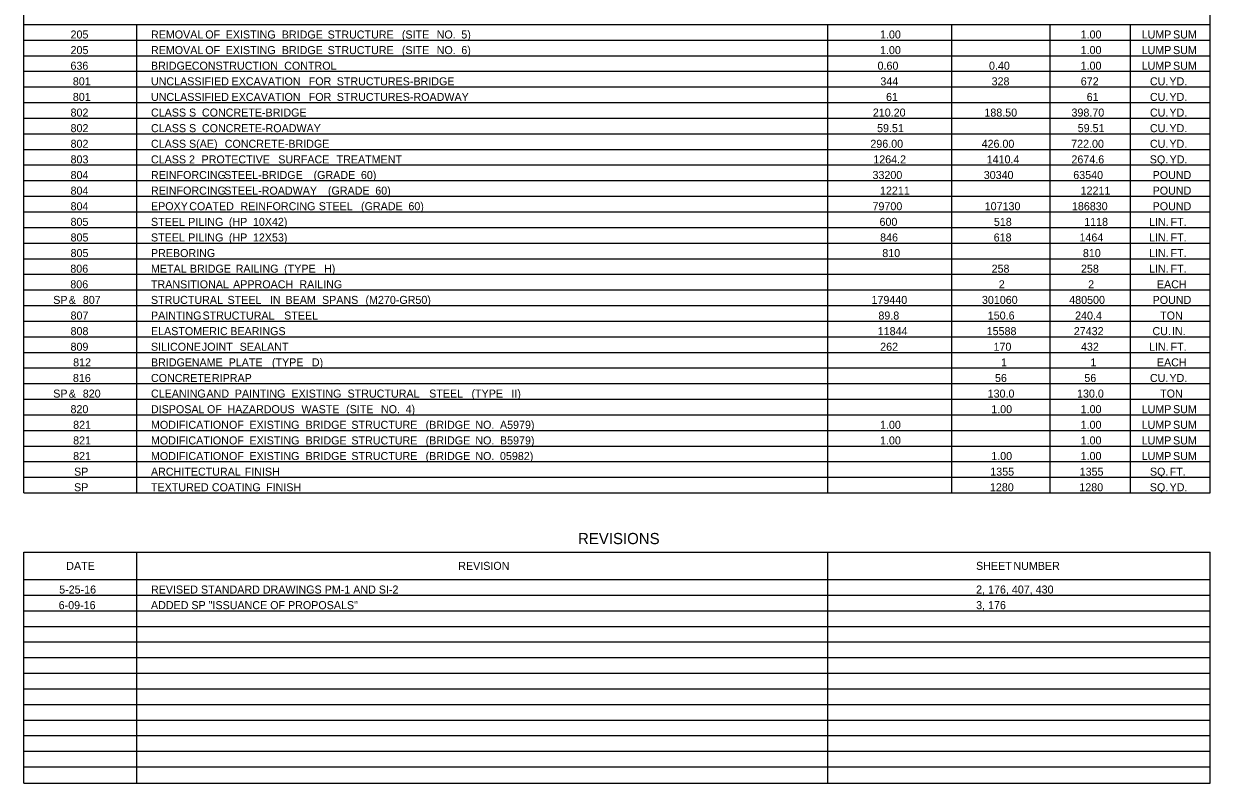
# Model space of a CAD drawing. Extents: x 1226912 to 1228117, y 151309 to 152323.
# Drawn here: x 1226912 to 1227653, y 151388 to 151863 of the extents above; entities that cross this region are included whole.
import ezdxf

# ---------------------------------------------------------------- set-up
doc = ezdxf.new("R2010")
doc.units = 0
doc.layers.add('R_Dimension', color=7, linetype='Continuous')

msp = doc.modelspace()

# ---------------------------------------------------------------- linework, layer by layer
at = {"layer": 'R_Dimension'}
for p, q in [((1226912.03, 151569.59), (1226912.03, 152184.82)), ((1227653.03, 151569.59), (1227653.03, 152184.82)), ((1226912.03, 151862.09), (1227653.03, 151862.09)), ((1226982.72, 151569.59), (1226982.72, 151862.09)), ((1227414.15, 151569.59), (1227414.15, 151862.09)), ((1227491.67, 151569.59), (1227491.67, 151862.09)), ((1227553.09, 151569.59), (1227553.09, 151862.09)), ((1227603.3, 151569.59), (1227603.3, 151862.09)), ((1226912.03, 151852.34), (1227653.03, 151852.34)), ((1226912.03, 151842.59), (1227653.03, 151842.59)), ((1226912.03, 151832.84), (1227653.03, 151832.84)), ((1226912.03, 151823.09), (1227653.03, 151823.09)), ((1226912.03, 151813.34), (1227653.03, 151813.34)), ((1226912.03, 151803.59), (1227653.03, 151803.59)), ((1226912.03, 151793.84), (1227653.03, 151793.84)), ((1226912.03, 151784.09), (1227653.03, 151784.09)), ((1226912.03, 151774.34), (1227653.03, 151774.34)), ((1226912.03, 151764.59), (1227653.03, 151764.59)), ((1226912.03, 151754.84), (1227653.03, 151754.84)), ((1226912.03, 151745.09), (1227653.03, 151745.09)), ((1226912.03, 151735.34), (1227653.03, 151735.34)), ((1226912.03, 151725.59), (1227653.03, 151725.59)), ((1226912.03, 151715.84), (1227653.03, 151715.84)), ((1226912.03, 151706.09), (1227653.03, 151706.09)), ((1226912.03, 151696.34), (1227653.03, 151696.34)), ((1226912.03, 151686.59), (1227653.03, 151686.59)), ((1226912.03, 151676.84), (1227653.03, 151676.84)), ((1226912.03, 151667.09), (1227653.03, 151667.09)), ((1226912.03, 151657.34), (1227653.03, 151657.34)), ((1226912.03, 151647.59), (1227653.03, 151647.59)), ((1226912.03, 151637.84), (1227653.03, 151637.84)), ((1226912.03, 151628.09), (1227653.03, 151628.09)), ((1226912.03, 151618.34), (1227653.03, 151618.34)), ((1226912.03, 151608.59), (1227653.03, 151608.59)), ((1226912.03, 151598.84), (1227653.03, 151598.84)), ((1226912.03, 151589.09), (1227653.03, 151589.09)), ((1226912.03, 151579.34), (1227653.03, 151579.34)), ((1226912.03, 151569.59), (1227653.03, 151569.59)), ((1226912.03, 151532.54), (1227653.03, 151532.54)), ((1226912.03, 151388.24), (1226912.03, 151532.54)), ((1226982.72, 151388.24), (1226982.72, 151532.54)), ((1227414.15, 151388.24), (1227414.15, 151532.54)), ((1227653.03, 151388.24), (1227653.03, 151532.54)), ((1226912.03, 151515.48), (1227653.03, 151515.48)), ((1226912.03, 151505.73), (1227653.03, 151505.73)), ((1226912.03, 151495.98), (1227653.03, 151495.98)), ((1226912.03, 151486.23), (1227653.03, 151486.23)), ((1226912.03, 151476.48), (1227653.03, 151476.48)), ((1226912.03, 151466.73), (1227653.03, 151466.73)), ((1226912.03, 151456.98), (1227653.03, 151456.98)), ((1226912.03, 151447.23), (1227653.03, 151447.23)), ((1226912.03, 151437.48), (1227653.03, 151437.48)), ((1226912.03, 151427.73), (1227653.03, 151427.73)), ((1226912.03, 151417.98), (1227653.03, 151417.98)), ((1226912.03, 151408.23), (1227653.03, 151408.23)), ((1226912.03, 151398.48), (1227653.03, 151398.48)), ((1226912.03, 151388.24), (1227653.03, 151388.24))]:
    msp.add_line(p, q, dxfattribs=at)

# ---------------------------------------------------------------- texts
for s, height, p in [('205', 5, (1226941.27, 151853.34)), ('REMOVAL', 5, (1226991.49, 151853.34)), (' OF', 5, (1227023.54, 151853.34)), (' EXISTING', 5, (1227036.3, 151853.34)), (' BRIDGE', 5, (1227071.33, 151853.34)), (' STRUCTURE', 5, (1227099.96, 151853.34)), (' (SITE', 5, (1227146.3, 151853.34)), (' NO.', 5, (1227168.07, 151853.34)), (' 5)', 5, (1227183.46, 151853.34)), ('1.00', 5, (1227446.79, 151853.34)), ('1.00', 5, (1227572.08, 151853.34)), ('LUMP', 5, (1227610.17, 151853.34)), (' SUM', 5, (1227627.93, 151853.34)), ('205', 5, (1226941.27, 151843.59)), ('REMOVAL', 5, (1226991.49, 151843.59)), (' OF', 5, (1227023.54, 151843.59)), (' EXISTING', 5, (1227036.3, 151843.59)), (' BRIDGE', 5, (1227071.33, 151843.59)), (' STRUCTURE', 5, (1227099.96, 151843.59)), (' (SITE', 5, (1227146.3, 151843.59)), (' NO.', 5, (1227168.07, 151843.59)), (' 6)', 5, (1227183.46, 151843.59)), ('1.00', 5, (1227446.79, 151843.59)), ('1.00', 5, (1227572.08, 151843.59)), ('LUMP', 5, (1227610.17, 151843.59)), (' SUM', 5, (1227627.93, 151843.59)), ('636', 5, (1226941.21, 151833.84)), ('BRIDGE', 5, (1226991.49, 151833.84)), (' CONSTRUCTION', 5, (1227015.11, 151833.84)), (' CONTROL', 5, (1227072.83, 151833.84)), ('0.60', 5, (1227445.25, 151833.84)), ('0.40', 5, (1227514.84, 151833.84)), ('1.00', 5, (1227572.08, 151833.84)), ('LUMP', 5, (1227610.17, 151833.84)), (' SUM', 5, (1227627.93, 151833.84)), ('801', 5, (1226942.69, 151824.09)), ('UNCLASSIFIED', 5, (1226991.49, 151824.09)), (' EXCAVATION', 5, (1227039.96, 151824.09)), (' FOR', 5, (1227088.15, 151824.09)), (' STRUCTURES-BRIDGE', 5, (1227105.63, 151824.09)), ('344', 5, (1227447.01, 151824.09)), ('328', 5, (1227516.47, 151824.09)), ('672', 5, (1227572.17, 151824.09)), ('CU.', 5, (1227615.35, 151824.09)), (' YD.', 5, (1227625.67, 151824.09)), ('801', 5, (1226942.69, 151814.34)), ('UNCLASSIFIED', 5, (1226991.49, 151814.34)), (' EXCAVATION', 5, (1227039.96, 151814.34)), (' FOR', 5, (1227088.15, 151814.34)), (' STRUCTURES-ROADWAY', 5, (1227105.63, 151814.34)), ('61', 5, (1227450.55, 151814.34)), ('61', 5, (1227575.84, 151814.34)), ('CU.', 5, (1227615.35, 151814.34)), (' YD.', 5, (1227625.67, 151814.34)), ('802', 5, (1226941.27, 151804.59)), ('CLASS', 5, (1226991.49, 151804.59)), (' S', 5, (1227013.38, 151804.59)), (' CONCRETE-BRIDGE', 5, (1227021.45, 151804.59)), ('210.20', 5, (1227442.3, 151804.59)), ('188.50', 5, (1227511.97, 151804.59)), ('398.70', 5, (1227566.37, 151804.59)), ('CU.', 5, (1227615.35, 151804.59)), (' YD.', 5, (1227625.67, 151804.59)), ('802', 5, (1226941.27, 151794.84)), ('CLASS', 5, (1226991.49, 151794.84)), (' S', 5, (1227013.38, 151794.84)), (' CONCRETE-ROADWAY', 5, (1227021.45, 151794.84)), ('59.51', 5, (1227444.96, 151794.84)), ('59.51', 5, (1227570.25, 151794.84)), ('CU.', 5, (1227615.35, 151794.84)), (' YD.', 5, (1227625.67, 151794.84)), ('802', 5, (1226941.27, 151785.09)), ('CLASS', 5, (1226991.49, 151785.09)), (' S(AE)', 5, (1227013.38, 151785.09)), (' CONCRETE-BRIDGE', 5, (1227035.7, 151785.09)), ('296.00', 5, (1227440.76, 151785.09)), ('426.00', 5, (1227510.23, 151785.09)), ('722.00', 5, (1227566.17, 151785.09)), ('CU.', 5, (1227615.35, 151785.09)), (' YD.', 5, (1227625.67, 151785.09)), ('803', 5, (1226941.27, 151775.34)), ('CLASS', 5, (1226991.49, 151775.34)), (' 2', 5, (1227013.38, 151775.34)), (' PROTECTIVE', 5, (1227021.22, 151775.34)), (' SURFACE', 5, (1227069.13, 151775.34)), (' TREATMENT', 5, (1227105.55, 151775.34)), ('1264.2', 5, (1227442.6, 151775.34)), ('1410.4', 5, (1227513.4, 151775.34)), ('2674.6', 5, (1227566.33, 151775.34)), ('SQ.', 5, (1227615.27, 151775.34)), (' YD.', 5, (1227625.75, 151775.34)), ('804', 5, (1226941.27, 151765.59)), ('REINFORCING', 5, (1226991.49, 151765.59)), (' STEEL-BRIDGE', 5, (1227035.39, 151765.59)), (' (GRADE', 5, (1227091.18, 151765.59)), (' 60)', 5, (1227120.74, 151765.59)), ('33200', 5, (1227442.1, 151765.59)), ('30340', 5, (1227511.57, 151765.59)), ('63540', 5, (1227567.47, 151765.59)), ('POUND', 5, (1227617.04, 151765.59)), ('804', 5, (1226941.27, 151755.84)), ('REINFORCING', 5, (1226991.49, 151755.84)), (' STEEL-ROADWAY', 5, (1227035.39, 151755.84)), (' (GRADE', 5, (1227100.15, 151755.84)), (' 60)', 5, (1227129.72, 151755.84)), ('12211', 5, (1227446.77, 151755.84)), ('12211', 5, (1227572.06, 151755.84)), ('POUND', 5, (1227617.04, 151755.84)), ('804', 5, (1226941.27, 151746.09)), ('EPOXY', 5, (1226991.49, 151746.09)), (' COATED', 5, (1227013.54, 151746.09)), (' REINFORCING', 5, (1227045.51, 151746.09)), (' STEEL', 5, (1227094.41, 151746.09)), (' (GRADE', 5, (1227120.82, 151746.09)), (' 60)', 5, (1227150.39, 151746.09)), ('79700', 5, (1227442.1, 151746.09)), ('107130', 5, (1227512.16, 151746.09)), ('186830', 5, (1227566.64, 151746.09)), ('POUND', 5, (1227617.04, 151746.09)), ('805', 5, (1226941.27, 151736.34)), ('STEEL', 5, (1226991.49, 151736.34)), (' PILING', 5, (1227012.91, 151736.34)), (' (HP', 5, (1227038.26, 151736.34)), (' 10X42)', 5, (1227053.3, 151736.34)), ('600', 5, (1227446.47, 151736.34)), ('518', 5, (1227517.89, 151736.34)), ('1118', 5, (1227574.3, 151736.34)), ('LIN.', 5, (1227614.76, 151736.34)), (' FT.', 5, (1227626.41, 151736.34)), ('805', 5, (1226941.27, 151726.59)), ('STEEL', 5, (1226991.49, 151726.59)), (' PILING', 5, (1227012.91, 151726.59)), (' (HP', 5, (1227038.26, 151726.59)), (' 12X53)', 5, (1227053.3, 151726.59)), ('846', 5, (1227446.87, 151726.59)), ('618', 5, (1227517.77, 151726.59)), ('1464', 5, (1227571.35, 151726.59)), ('LIN.', 5, (1227614.76, 151726.59)), (' FT.', 5, (1227626.41, 151726.59)), ('805', 5, (1226941.27, 151716.84)), ('PREBORING', 5, (1226991.49, 151716.84)), ('810', 5, (1227448.21, 151716.84)), ('810', 5, (1227573.49, 151716.84)), ('LIN.', 5, (1227614.76, 151716.84)), (' FT.', 5, (1227626.41, 151716.84)), (' (TYPE', 5, (1227072.79, 151707.09)), (' H)', 5, (1227097.71, 151707.09)), ('806', 5, (1226941.13, 151707.09)), ('METAL', 5, (1226991.49, 151707.09)), (' BRIDGE', 5, (1227013.93, 151707.09)), (' RAILING', 5, (1227042.55, 151707.09)), ('258', 5, (1227516.47, 151707.09)), ('258', 5, (1227572.29, 151707.09)), ('LIN.', 5, (1227614.76, 151707.09)), (' FT.', 5, (1227626.41, 151707.09)), ('806', 5, (1226941.13, 151697.34)), ('TRANSITIONAL', 5, (1226991.49, 151697.34)), (' APPROACH', 5, (1227040.94, 151697.34)), (' RAILING', 5, (1227082.32, 151697.34)), ('2', 5, (1227520.96, 151697.34)), ('2', 5, (1227576.78, 151697.34)), ('EACH', 5, (1227619.7, 151697.34)), ('SP', 5, (1226930.46, 151687.59)), (' &', 5, (1226938.3, 151687.59)), (' 807', 5, (1226947.08, 151687.59)), ('STRUCTURAL', 5, (1226991.49, 151687.59)), (' STEEL', 5, (1227037.48, 151687.59)), (' IN', 5, (1227063.89, 151687.59)), (' BEAM', 5, (1227073.66, 151687.59)), (' SPANS', 5, (1227096.45, 151687.59)), (' (M270-GR50)', 5, (1227123.58, 151687.59)), ('179440', 5, (1227441.47, 151687.59)), ('301060', 5, (1227510.43, 151687.59)), ('480500', 5, (1227564.95, 151687.59)), ('POUND', 5, (1227617.04, 151687.59)), ('807', 5, (1226941.27, 151677.84)), ('PAINTING', 5, (1226991.49, 151677.84)), (' STRUCTURAL', 5, (1227021.85, 151677.84)), (' STEEL', 5, (1227072.83, 151677.84)), ('89.8', 5, (1227445.78, 151677.84)), ('150.6', 5, (1227514.09, 151677.84)), ('240.4', 5, (1227568.63, 151677.84)), ('TON', 5, (1227621.73, 151677.84)), ('808', 5, (1226941.27, 151668.09)), ('ELASTOMERIC', 5, (1226991.49, 151668.09)), (' BEARINGS', 5, (1227039.17, 151668.09)), ('11844', 5, (1227445.35, 151668.09)), ('15588', 5, (1227513.4, 151668.09)), ('27432', 5, (1227567.8, 151668.09)), ('CU.', 5, (1227616.93, 151668.09)), (' IN.', 5, (1227627.24, 151668.09)), ('809', 5, (1226941.25, 151658.34)), ('SILICONE', 5, (1226991.49, 151658.34)), (' JOINT', 5, (1227021.41, 151658.34)), (' SEALANT', 5, (1227045.04, 151658.34)), ('262', 5, (1227446.89, 151658.34)), ('170', 5, (1227517.67, 151658.34)), ('432', 5, (1227572.29, 151658.34)), ('LIN.', 5, (1227614.76, 151658.34)), (' FT.', 5, (1227626.41, 151658.34)), ('812', 5, (1226942.88, 151648.59)), ('BRIDGE', 5, (1226991.49, 151648.59)), (' NAME', 5, (1227015.11, 151648.59)), (' PLATE', 5, (1227038.15, 151648.59)), (' (TYPE', 5, (1227065.19, 151648.59)), (' D)', 5, (1227090.11, 151648.59)), ('1', 5, (1227522.38, 151648.59)), ('1', 5, (1227578.2, 151648.59)), ('EACH', 5, (1227619.7, 151648.59)), ('816', 5, (1226942.75, 151638.84)), ('CONCRETE', 5, (1226991.49, 151638.84)), (' RIPRAP', 5, (1227027.71, 151638.84)), ('56', 5, (1227518.58, 151638.84)), ('56', 5, (1227574.4, 151638.84)), ('CU.', 5, (1227615.35, 151638.84)), (' YD.', 5, (1227625.67, 151638.84)), ('SP', 5, (1226930.44, 151629.09)), (' &', 5, (1226938.28, 151629.09)), (' 820', 5, (1226947.06, 151629.09)), ('CLEANING', 5, (1226991.49, 151629.09)), (' AND', 5, (1227024.29, 151629.09)), (' PAINTING', 5, (1227042, 151629.09)), (' EXISTING', 5, (1227077.36, 151629.09)), (' STRUCTURAL', 5, (1227112.4, 151629.09)), (' STEEL', 5, (1227163.38, 151629.09)), (' (TYPE', 5, (1227189.8, 151629.09)), (' II)', 5, (1227214.72, 151629.09)), ('130.0', 5, (1227514.01, 151629.09)), ('130.0', 5, (1227569.83, 151629.09)), ('TON', 5, (1227621.73, 151629.09)), ('820', 5, (1226941.25, 151619.34)), ('DISPOSAL', 5, (1226991.49, 151619.34)), (' OF', 5, (1227024.64, 151619.34)), (' HAZARDOUS', 5, (1227037.4, 151619.34)), (' WASTE', 5, (1227083.58, 151619.34)), (' (SITE', 5, (1227111.49, 151619.34)), (' NO.', 5, (1227133.26, 151619.34)), (' 4)', 5, (1227148.66, 151619.34)), ('1.00', 5, (1227516.26, 151619.34)), ('1.00', 5, (1227572.08, 151619.34)), ('LUMP', 5, (1227610.17, 151619.34)), (' SUM', 5, (1227627.93, 151619.34)), ('821', 5, (1226942.88, 151609.59)), ('MODIFICATION', 5, (1226991.49, 151609.59)), (' OF', 5, (1227038.38, 151609.59)), (' EXISTING', 5, (1227051.14, 151609.59)), (' BRIDGE', 5, (1227086.18, 151609.59)), (' STRUCTURE', 5, (1227114.8, 151609.59)), (' (BRIDGE', 5, (1227161.14, 151609.59)), (' NO.', 5, (1227192.2, 151609.59)), (' A5979)', 5, (1227207.59, 151609.59)), ('1.00', 5, (1227446.79, 151609.59)), ('1.00', 5, (1227572.08, 151609.59)), ('LUMP', 5, (1227610.17, 151609.59)), (' SUM', 5, (1227627.93, 151609.59)), ('821', 5, (1226942.88, 151599.84)), ('MODIFICATION', 5, (1226991.49, 151599.84)), (' OF', 5, (1227038.38, 151599.84)), (' EXISTING', 5, (1227051.14, 151599.84)), (' BRIDGE', 5, (1227086.18, 151599.84)), (' STRUCTURE', 5, (1227114.8, 151599.84)), (' (BRIDGE', 5, (1227161.14, 151599.84)), (' NO.', 5, (1227192.2, 151599.84)), (' B5979)', 5, (1227207.59, 151599.84)), ('1.00', 5, (1227446.79, 151599.84)), ('1.00', 5, (1227572.08, 151599.84)), ('LUMP', 5, (1227610.17, 151599.84)), (' SUM', 5, (1227627.93, 151599.84)), ('821', 5, (1226942.88, 151590.09)), ('MODIFICATION', 5, (1226991.49, 151590.09)), (' OF', 5, (1227038.38, 151590.09)), (' EXISTING', 5, (1227051.14, 151590.09)), (' BRIDGE', 5, (1227086.18, 151590.09)), (' STRUCTURE', 5, (1227114.8, 151590.09)), (' (BRIDGE', 5, (1227161.14, 151590.09)), (' NO.', 5, (1227192.2, 151590.09)), (' 05982)', 5, (1227207.59, 151590.09)), ('1.00', 5, (1227516.26, 151590.09)), ('1.00', 5, (1227572.08, 151590.09)), ('LUMP', 5, (1227610.17, 151590.09)), (' SUM', 5, (1227627.93, 151590.09)), ('SP', 5, (1226943.46, 151580.34)), ('ARCHITECTURAL', 5, (1226991.49, 151580.34)), (' FINISH', 5, (1227048.18, 151580.34)), ('1355', 5, (1227515.65, 151580.34)), ('1355', 5, (1227571.47, 151580.34)), ('SQ.', 5, (1227615.35, 151580.34)), (' FT.', 5, (1227625.82, 151580.34)), ('SP', 5, (1226943.46, 151570.59)), ('TEXTURED', 5, (1226991.49, 151570.59)), (' COATING', 5, (1227027.67, 151570.59)), (' FINISH', 5, (1227061.53, 151570.59)), ('1280', 5, (1227515.43, 151570.59)), ('1280', 5, (1227571.25, 151570.59)), ('SQ.', 5, (1227615.27, 151570.59)), (' YD.', 5, (1227625.75, 151570.59)), ('REVISIONS', 7, (1227258.17, 151537.57)), ('DATE', 5, (1226938.59, 151521.51)), ('REVISION', 5, (1227183.38, 151521.51)), ('SHEET', 5, (1227506.76, 151521.51)), (' NUMBER', 5, (1227528.22, 151521.51)), ('5-25-16', 5, (1226934.16, 151506.73)), ('REVISED STANDARD DRAWINGS PM-1 AND SI-2', 5, (1226991.49, 151506.73)), ('2, 176, 407, 430', 5, (1227506.82, 151506.73)), ('6-09-16', 5, (1226933.85, 151496.98)), ('ADDED SP "ISSUANCE OF PROPOSALS" ', 5, (1226991.49, 151496.98)), ('3, 176', 5, (1227506.82, 151496.98))]:
    msp.add_text(s, height=height, dxfattribs=at).set_placement(p)

doc.saveas('drawing.dxf')
